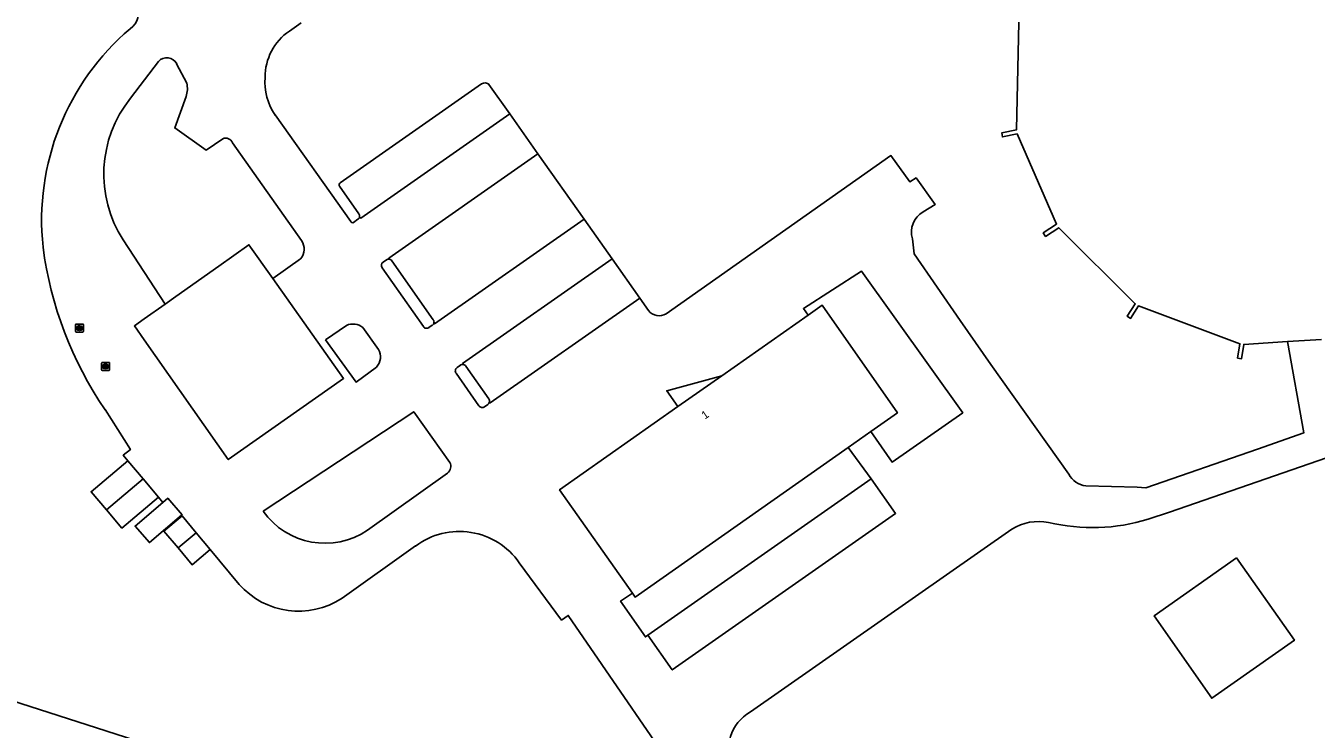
# Model space of a CAD drawing. Extents: x 162722 to 165099, y 384721 to 386283.
# Drawn here: x 162985.2 to 163146.5, y 385557.6 to 385645.6 of the extents above; entities that cross this region are included whole.
import ezdxf

# ---------------------------------------------------------------- set-up
doc = ezdxf.new("R2010")
doc.units = 0
for name, color, linetype in [('IMGEO_Gemengd_bos', 7, 'Continuous'), ('IMGEO_Hek', 7, 'Continuous'), ('IMGEO_Opslagtank', 7, 'Continuous'), ('IMGEO_Pand', 7, 'Continuous'), ('IMGEO_Pand_nummerreeks', 7, 'Continuous'), ('IMGEO_Pand_overbouw', 7, 'Continuous'), ('IMGEO_Parkeervlak_open', 7, 'Continuous'), ('IMGEO_Rijbaan_lokaal_gesloten', 7, 'Continuous'), ('IMGEO_Rioolput', 7, 'Continuous')]:
    doc.layers.add(name, color=color, linetype=linetype)

msp = doc.modelspace()

# ---------------------------------------------------------------- linework, layer by layer
at = {"layer": 'IMGEO_Gemengd_bos'}
msp.add_lwpolyline([(162941.78, 385601.6), (162943.36, 385599.2), (162964.2, 385567.38), (163064.48, 385535.1), (163132.9, 385437.69)], dxfattribs=at)
at = {"layer": 'IMGEO_Hek'}
msp.add_lwpolyline([(163064.48, 385535.1), (162964.2, 385567.38), (162943.36, 385599.2)], dxfattribs=at)
at = {"layer": 'IMGEO_Opslagtank'}
for points in [[(163109.31, 385646.07), (163109.02, 385632.58), (163107.2, 385632.21), (163107.28, 385631.71), (163109.1, 385632.08), (163114.04, 385620.8), (163112.39, 385619.7), (163112.67, 385619.27), (163114.31, 385620.36), (163123.87, 385610.85), (163122.88, 385609.29), (163123.29, 385609.01), (163124.28, 385610.57), (163136.96, 385605.83), (163136.68, 385604.04), (163137.17, 385603.96), (163137.45, 385605.75), (163142.93, 385606.11)], [(163142.93, 385606.11), (163147.16, 385606.38)]]:
    msp.add_lwpolyline(points, dxfattribs=at)
at = {"layer": 'IMGEO_Pand'}
for points in [[(163002.64, 385610.81), (163003.97, 385611.75), (163009.33, 385615.55), (163013.09, 385618.22), (163016.08, 385614)], [(163016.08, 385614), (163024.93, 385601.5), (163010.51, 385591.35), (163000, 385606.31), (162998.77, 385608.07), (163000, 385608.94), (163002.64, 385610.81)], [(163090.83, 385594.86), (163094.16, 385597.2), (163084.75, 385610.66), (163082.99, 385609.42)], [(163082.99, 385609.42), (163072.2, 385601.84), (163066.71, 385597.98), (163051.92, 385587.58), (163061.02, 385574.64)], [(163088, 385592.87), (163090.83, 385594.86)], [(163088, 385592.87), (163061.37, 385574.14), (163061.02, 385574.64)], [(162995.3, 385585.06), (162993.37, 385587.33), (162997.94, 385591.21)], [(162999.87, 385588.93), (162997.94, 385591.21)], [(162999.87, 385588.93), (162995.3, 385585.06)], [(163001.8, 385586.65), (162999.87, 385588.93)], [(163001.8, 385586.65), (162997.22, 385582.79), (162995.3, 385585.06)], [(163002.34, 385585.99), (163002.95, 385586.51), (163004.73, 385584.45), (163004.67, 385584.4)], [(163004.67, 385584.4), (163000.65, 385580.96), (162998.86, 385583.03), (163002.34, 385585.99)], [(163004.23, 385580.3), (163002.47, 385582.4), (163004.76, 385584.32)], [(163006.51, 385582.2), (163004.76, 385584.32)], [(163006.51, 385582.2), (163004.23, 385580.3)], [(163008.26, 385580.09), (163006.51, 385582.2)], [(163008.26, 385580.09), (163005.98, 385578.19), (163004.23, 385580.3)], [(163136.54, 385579.04), (163143.78, 385568.74), (163133.45, 385561.5), (163126.23, 385571.8), (163136.54, 385579.04)]]:
    msp.add_lwpolyline(points, dxfattribs=at)
at = {"layer": 'IMGEO_Pand_overbouw'}
msp.add_lwpolyline([(163072.2, 385601.84), (163065.31, 385599.96), (163066.71, 385597.98)], close=True, dxfattribs=at)
at = {"layer": 'IMGEO_Parkeervlak_open'}
for points in [[(163042.17, 385638.36), (163024.5, 385625.96)], [(163045.69, 385634.6), (163043.1, 385638.27)], [(163049.21, 385629.61), (163054.98, 385621.44)], [(163024.42, 385625.54), (163026.84, 385622.1)], [(163036.14, 385608.84), (163030.97, 385616.21)], [(163058.49, 385616.46), (163061.95, 385611.56)], [(163043.08, 385598.93), (163040.21, 385603.03)], [(163090.89, 385588.96), (163062.97, 385569.38)]]:
    msp.add_lwpolyline(points, dxfattribs=at)
for centre, radius, start, end in [((163042.58, 385637.69), 0.779, 47.4867, 121.0799), ((163024.67, 385625.72), 0.3, 125.1352, 215.0522), ((163026.42, 385621.81), 0.506, 350.7895, 34.7923), ((163030.56, 385615.93), 0.495, 34.8806, 80.3149), ((163035.73, 385608.56), 0.498, 349.8739, 35.1513), ((163039.81, 385602.75), 0.495, 34.8806, 80.3149), ((163042.68, 385598.65), 0.498, 349.8739, 35.1513)]:
    msp.add_arc(centre, radius, start, end, dxfattribs=at)
at = {"layer": 'IMGEO_Rijbaan_lokaal_gesloten'}
for points in [[(163019.62, 385645.99), (163018.15, 385644.95)], [(162998.29, 385636.55), (163001.79, 385641.16)], [(163004.06, 385640.87), (163005.33, 385638.44)], [(163005.26, 385636.77), (163003.82, 385632.85), (163007.76, 385630.07), (163009.82, 385631.49)], [(163026.92, 385621.73), (163027.06, 385621.53), (163045.69, 385634.6)], [(163045.69, 385634.6), (163049.21, 385629.61)], [(163016.38, 385634.46), (163025.82, 385621.12)], [(163011.04, 385630.99), (163019.68, 385618.75)], [(163049.21, 385629.61), (163030.56, 385616.54), (163030.64, 385616.42)], [(163065.25, 385609.6), (163093.34, 385629.37), (163095.72, 385626.09), (163096.49, 385626.58), (163098.88, 385623.27), (163097.39, 385622.34)], [(163026.17, 385621.01), (163026.72, 385621.41)], [(163036.22, 385608.47), (163036.3, 385608.35), (163054.98, 385621.44)], [(163054.98, 385621.44), (163058.49, 385616.46)], [(163002.64, 385610.81), (162997.36, 385618.85)], [(163096.03, 385618.97), (163096.25, 385617.08), (163102, 385608.75), (163105.84, 385603.24), (163115.59, 385589.53)], [(163019.55, 385616.46), (163016.08, 385614)], [(163029.74, 385615.35), (163034.91, 385607.98)], [(163030.27, 385616.33), (163029.86, 385616.05)], [(163058.49, 385616.46), (163039.8, 385603.35), (163039.89, 385603.23)], [(163090.83, 385594.86), (163093.49, 385591.04), (163102.31, 385597.21), (163089.65, 385614.94), (163082.4, 385610.24), (163082.99, 385609.42)], [(163043.17, 385598.56), (163043.25, 385598.44), (163061.95, 385611.56)], [(163061.95, 385611.56), (163063.05, 385610.01)], [(163022.68, 385606.34), (163025.28, 385608.14)], [(163027.32, 385607.86), (163029.27, 385605.13)], [(163035.6, 385607.86), (163036.01, 385608.15)], [(163029.03, 385602.91), (163026.49, 385601.05), (163022.68, 385606.34)], [(163117.7, 385588.08), (163124.1, 385587.89), (163125.22, 385587.83), (163139.18, 385592.66), (163144.96, 385594.7), (163142.93, 385606.11)], [(163197.61, 385604.63), (163174.02, 385600.67), (163128.15, 385584.79), (163125.49, 385583.9)], [(163039.52, 385603.15), (163039.11, 385602.86)], [(163038.98, 385602.17), (163041.85, 385598.07)], [(162997.94, 385591.21), (162997.38, 385591.89), (162998.27, 385592.61), (162995.11, 385597.6)], [(163042.55, 385597.95), (163042.96, 385598.24)], [(163014.87, 385584.9), (163033.69, 385597.34), (163038.22, 385591)], [(163090.89, 385588.96), (163088, 385592.87)], [(163037.93, 385589.64), (163027.93, 385582.52)], [(163062.97, 385569.38), (163066.01, 385565.04), (163093.93, 385584.62), (163090.89, 385588.96)], [(163002.34, 385585.99), (163001.8, 385586.65)], [(163004.76, 385584.32), (163004.67, 385584.4)], [(163108.47, 385582.63), (163075.78, 385559.78)], [(163011.86, 385575.74), (163008.26, 385580.09)], [(163033.93, 385580.54), (163024.74, 385574.01)], [(163144.21, 385429.1), (163144.61, 385431.59), (163144.74, 385434.44), (163144.37, 385437.6), (163144.01, 385440.61), (163141.97, 385444.78), (163138.95, 385449.42), (163112.11, 385487.52), (163076.77, 385537.55), (163069.39, 385548), (163053.01, 385571.86), (163052.18, 385571.27), (163046.88, 385578.45)], [(163061.02, 385574.64), (163059.55, 385573.64), (163062.66, 385569.16), (163062.97, 385569.38)]]:
    msp.add_lwpolyline(points, dxfattribs=at)
for centre, radius, start, end in [((162996.93, 385647.19), 2.35, 304.1975, 28.2774), ((163018.64, 385621.29), 31.46, 130.3993, 186.1245), ((163022.12, 385639.18), 7.01, 124.5523, 180.1373), ((163002.83, 385640.25), 1.38, 26.6195, 138.6534), ((163002.26, 385637.74), 3.14, 341.9386, 12.7847), ((163022.46, 385638.62), 7.37, 175.7766, 214.4119), ((163010.11, 385627.05), 15.16, 141.2236, 212.7756), ((163010.18, 385630.62), 0.939, 23.3051, 112.6244), ((163026.43, 385621.81), 0.501, 305.9404, 350.3692), ((163098.79, 385619.81), 2.89, 118.9999, 197.0347), ((163026.05, 385621.23), 0.251, 203.9061, 298.8315), ((163018.08, 385617.69), 1.92, 320.2162, 33.6348), ((163033.82, 385623.99), 46.86, 187.4334, 214.2858), ((163030.15, 385615.64), 0.5, 125.1104, 215.0051), ((163030.56, 385615.93), 0.494, 79.7876, 125.3026), ((163064.36, 385610.93), 1.6, 215.292, 303.9286), ((163026.08, 385606.39), 1.92, 49.7517, 114.6954), ((163035.32, 385608.27), 0.499, 214.9043, 305.0515), ((163035.73, 385608.55), 0.496, 304.9062, 350.1284), ((163027.63, 385604.19), 1.9, 317.4213, 29.8757), ((163039.39, 385602.45), 0.499, 124.9043, 215.0515), ((163039.8, 385602.74), 0.498, 79.8739, 125.1513), ((163042.26, 385598.36), 0.5, 214.9509, 305.0332), ((163042.68, 385598.65), 0.496, 304.9062, 350.1284), ((163037.14, 385590.52), 1.18, 311.7615, 23.8767), ((163117.92, 385590.65), 2.59, 205.7079, 264.9868), ((163022.61, 385590.35), 9.47, 215.125, 304.1966), ((163111.85, 385577.26), 6.35, 79.1624, 122.2717), ((163118.54, 385606.33), 23.49, 256.4827, 287.2181), ((163039.4, 385573.25), 9.11, 34.7981, 126.8802), ((163019.31, 385582.35), 9.96, 221.6028, 303.0663), ((163078.42, 385555.1), 5.37, 119.3733, 205.9029)]:
    msp.add_arc(centre, radius, start, end, dxfattribs=at)
at = {"layer": 'IMGEO_Rioolput'}
for p, q in [((162991.42, 385607.36), (162991.42, 385608.22)), ((162991.49, 385608.29), (162992.34, 385608.29)), ((162992.34, 385607.29), (162991.49, 385607.29)), ((162991.9, 385608.07), (162991.93, 385608.07)), ((162991.93, 385607.51), (162991.9, 385607.51)), ((162992.42, 385608.22), (162992.42, 385607.36)), ((162994.67, 385602.58), (162994.67, 385603.43)), ((162994.75, 385603.5), (162995.6, 385603.5)), ((162995.6, 385602.5), (162994.75, 385602.5)), ((162995.16, 385603.28), (162995.18, 385603.28)), ((162995.18, 385602.72), (162995.16, 385602.72)), ((162995.67, 385603.43), (162995.67, 385602.58))]:
    msp.add_line(p, q, dxfattribs=at)
for points in [[(162991.42, 385607.36), (162991.42, 385608.22)], [(162991.49, 385608.29), (162992.34, 385608.29)], [(162992.34, 385607.29), (162991.49, 385607.29)], [(162992, 385607.99), (162991.75, 385607.99), (162991.75, 385607.59)], [(162991.75, 385607.59), (162991.88, 385607.59), (162991.88, 385607.75), (162991.89, 385607.75)], [(162991.93, 385607.91), (162991.88, 385607.91), (162991.88, 385607.83)], [(162991.88, 385607.83), (162991.93, 385607.83)], [(162991.93, 385607.72), (162992.01, 385607.59), (162992.14, 385607.59), (162992.08, 385607.72)], [(162992.42, 385608.22), (162992.42, 385607.36)], [(162994.67, 385602.58), (162994.67, 385603.43)], [(162994.75, 385603.5), (162995.6, 385603.5)], [(162995.6, 385602.5), (162994.75, 385602.5)], [(162995.26, 385603.2), (162995.01, 385603.2), (162995.01, 385602.8)], [(162995.01, 385602.8), (162995.13, 385602.8), (162995.13, 385602.97), (162995.14, 385602.97)], [(162995.19, 385603.12), (162995.13, 385603.12), (162995.13, 385603.04)], [(162995.13, 385603.04), (162995.18, 385603.04)], [(162995.19, 385602.94), (162995.26, 385602.8), (162995.4, 385602.8), (162995.34, 385602.93)], [(162995.67, 385603.43), (162995.67, 385602.58)]]:
    msp.add_lwpolyline(points, dxfattribs=at)
for centre, radius, start, end in [((162991.49, 385608.22), 0.0765, 91.552, 178.448), ((162991.49, 385608.22), 0.0765, 91.552, 178.448), ((162991.49, 385607.37), 0.0765, 181.552, 268.448), ((162991.49, 385607.37), 0.0765, 181.552, 268.448), ((162991.89, 385607.7), 0.0533, 26.0293, 88.6989), ((162991.94, 385607.81), 0.0964, 77.0061, 93.1865), ((162991.91, 385608.02), 0.19, 274.7715, 282.9687), ((162991.95, 385607.87), 0.0378, 276.6634, 79.6772), ((162992, 385607.88), 0.109, 350.3612, 89.416), ((162992, 385607.88), 0.112, 277.5842, 350.9817), ((162991.99, 385607.66), 0.108, 29.5134, 73.7905), ((162992.34, 385608.22), 0.0765, 1.552, 88.448), ((162992.34, 385608.22), 0.0765, 1.552, 88.448), ((162992.34, 385607.37), 0.0765, 271.552, 358.448), ((162992.34, 385607.37), 0.0765, 271.552, 358.448), ((162994.75, 385603.43), 0.0765, 91.552, 178.448), ((162994.75, 385603.43), 0.0765, 91.552, 178.448), ((162994.75, 385602.58), 0.0765, 181.552, 268.448), ((162994.75, 385602.58), 0.0765, 181.552, 268.448), ((162995.14, 385602.91), 0.0533, 26.0293, 88.6989), ((162995.17, 385603.23), 0.19, 274.7715, 282.9687), ((162995.19, 385603.03), 0.0964, 77.0061, 93.1865), ((162995.21, 385603.08), 0.0378, 276.6634, 79.6772), ((162995.26, 385603.09), 0.109, 350.3612, 89.416), ((162995.26, 385603.09), 0.112, 277.5842, 350.9817), ((162995.24, 385602.88), 0.108, 29.5134, 73.7905), ((162995.6, 385603.43), 0.0765, 1.552, 88.448), ((162995.6, 385603.43), 0.0765, 1.552, 88.448), ((162995.6, 385602.58), 0.0765, 271.552, 358.448), ((162995.6, 385602.58), 0.0765, 271.552, 358.448)]:
    msp.add_arc(centre, radius, start, end, dxfattribs=at)
for centre, major_axis, ratio, start_param, end_param in [((162991.9, 385607.79), (-0.387, 0.002), 0.722429, 4.712389, 7.853982), ((162991.93, 385607.79), (-0.39, 0.002), 0.717154, 1.570796, 4.712389), ((162995.16, 385603), (-0.387, 0.002), 0.722429, 4.712389, 7.853982), ((162995.18, 385603), (-0.39, 0.002), 0.717154, 1.570796, 4.712389)]:
    msp.add_ellipse(centre, major_axis=major_axis, ratio=ratio, start_param=start_param, end_param=end_param, dxfattribs=at)

# ---------------------------------------------------------------- texts
at = {"layer": 'IMGEO_Pand_nummerreeks'}
msp.add_text('1', height=1, rotation=35.1051, dxfattribs=at).set_placement((163070.09, 385596.34))

doc.saveas('drawing.dxf')
